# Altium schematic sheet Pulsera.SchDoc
size A4; SheetNumber: 1; SheetTotal: 1
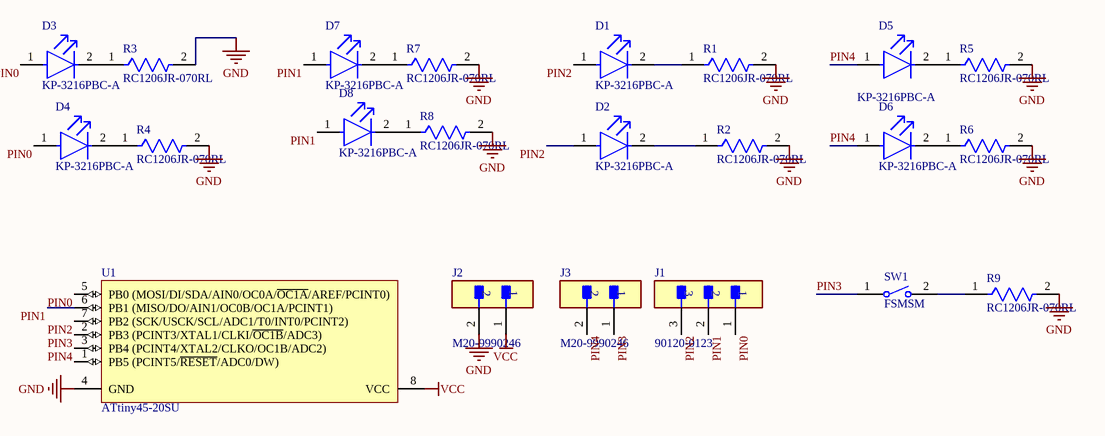
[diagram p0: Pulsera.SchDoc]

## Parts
D1  KP-3216PBC-A  [FP-KP-3216PBC-A-MFG]
D2  KP-3216PBC-A  [FP-KP-3216PBC-A-MFG]
D3  KP-3216PBC-A  [FP-KP-3216PBC-A-MFG]
D4  KP-3216PBC-A  [FP-KP-3216PBC-A-MFG]
D5  KP-3216PBC-A  [FP-KP-3216PBC-A-MFG]
D6  KP-3216PBC-A  [FP-KP-3216PBC-A-MFG]
D7  KP-3216PBC-A  [FP-KP-3216PBC-A-MFG]
D8  KP-3216PBC-A  [FP-KP-3216PBC-A-MFG]
J1  90120-0123  [FP-90120-0123-MFG]
J2  M20-9990246  [FP-M20-9990246-MFG]
J3  M20-9990246  [FP-M20-9990246-MFG]
R1  RC1206JR-070RL  [FP-RC1206-MFG]
R2  RC1206JR-070RL  [FP-RC1206-MFG]
R3  RC1206JR-070RL  [FP-RC1206-MFG]
R4  RC1206JR-070RL  [FP-RC1206-MFG]
R5  RC1206JR-070RL  [FP-RC1206-MFG]
R6  RC1206JR-070RL  [FP-RC1206-MFG]
R7  RC1206JR-070RL  [FP-RC1206-MFG]
R8  RC1206JR-070RL  [FP-RC1206-MFG]
R9  RC1206JR-070RL  [FP-RC1206-MFG]
SW1  FSMSM  [TECO-FSMSM-2_V]
U1  ATtiny45-20SU  [8S2_M]

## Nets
GND: J2.2 R1.2 R2.2 R3.2 R4.2 R5.2 R6.2 R7.2 R8.2 R9.2 U1.4(GND)
VCC: J2.1 U1.8(VCC)
PIN0: D3.1(A) D4.1(A) J1.1 U1.5(PB0_(MOSI/DI/SDA/AIN0/OC0A/~{OC1A}/AREF/PCINT0))
PIN1: D7.1(A) D8.1(A) J1.2 U1.6(PB1_(MISO/DO/AIN1/OC0B/OC1A/PCINT1))
PIN2: D1.1(A) D2.1(A) J1.3 U1.7(PB2_(SCK/USCK/SCL/ADC1/T0/INT0/PCINT2))
PIN3: J3.1 SW1.1 U1.2(PB3_(PCINT3/XTAL1/CLKI/~{OC1B}/ADC3))
PIN4: D5.1(A) D6.1(A) J3.2 U1.3(PB4_(PCINT4/XTAL2/CLKO/OC1B/ADC2))
NetD1_2: D1.2(C) R1.1
NetD2_2: D2.2(C) R2.1
NetD3_2: D3.2(C) R3.1
NetD4_2: D4.2(C) R4.1
NetD5_2: D5.2(C) R5.1
NetD6_2: D6.2(C) R6.1
NetD7_2: D7.2(C) R7.1
NetD8_2: D8.2(C) R8.1
NetR9_1: R9.1 SW1.2

Not connected (* = marked no-connect by the designer): U1 1(PB5_(PCINT5/~{RESET}/ADC0/DW))

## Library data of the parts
D1-D8 = CMP-44529-000052-1: LED, Low Power, Blue, SMD, 1.6mm x 2mm, 20 mA, 3.2 V, 470 nm; Forward Voltage: 3.2V; Wavelength: 470nm; Luminous Intensity: 60mcd; Lens Color: Clear; Forward Current: 20mA; Viewing Angle: 120°; Number of LEDs: 1; Lens Style: Rectangular
J1 = CMP-04776-000237-1: CONN HEADER VERT 3POS 2.54MM; Number of Circuits: 3; Max Voltage Rating (DC): 350.35kV; Contact Resistance: 20mR; Gender: Male; Voltage Rating (AC): 350V; Glow Wire Compliant: Non-compliant; Current Rating: 3A; Contact Post Length: 2.9mm
J2 J3 = CMP-15831-000009-1: CONN HEADER VERT 2POS 2.54MM; Manufacturer: Harwin; Conn Gender: Male; Conn Orientation: Vertical; Number Of Contacts: 2; Current Rating: 3A
R1-R9 = CMP-2100-03681-2: RES SMD 0 OHM JUMPER 1/4W 1206; Manufacturer: YAGEO; Voltage Rating: 200V; Temperature Coefficient: 300ppm/°C; Power Rating: 0.25W; Value: 0Ω; Tolerance: 5%
SW1 = CMP-2000-07511-1: FSMSM Push Button Switch, 50 mA, -35 to 85 degC, 2-Pin SMD, RoHS, Bulk; Manufacturer: TE Connectivity; Actuator Length: 1.07mm; Electrical Life: 20000Cycles; Actuator Material: Polyamide; Current Rating: 50mA; Illumination Type: Illuminated; Voltage Rating (DC): 24V; Contact Resistance: 100mOhm; Case\/Package: SMD/SMT; Operating Force: 180gf; Switch Travel: 0.25mm; Max Voltage Rating (DC): 12V; Throw Configuration: SPST
U1 = CMP-0093-00180-2: 8-bit AVR Microcontroller, 20MHz, 2.7-5.5V, 4K Flash, 256 Bytes EEPROM, 256 Bytes SRAM, Industrial Grade (-40°C to 85°C), 8-Lead SOIC, Pb-Free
